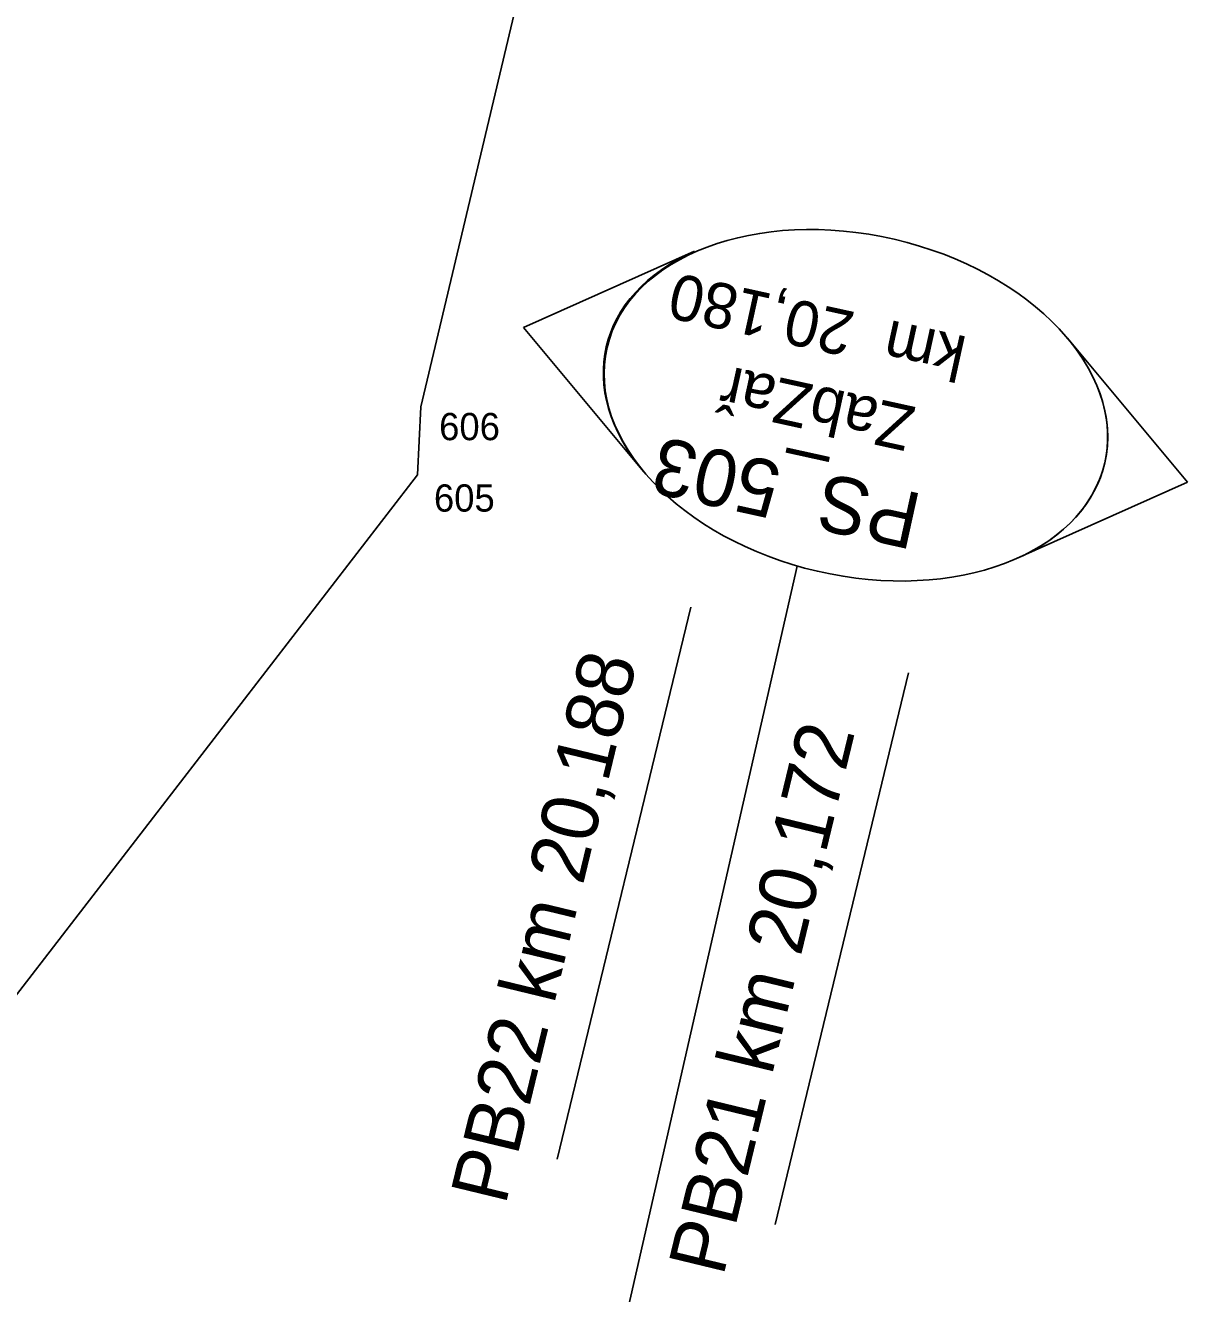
# Model space of a CAD drawing. Extents: x -748344 to -743169, y -1131966 to -1127091.
# Drawn here: x -747617.2 to -747566.1, y -1131689.4 to -1131633.6 of the extents above; entities that cross this region are included whole.
import ezdxf

# ---------------------------------------------------------------- set-up
doc = ezdxf.new("R2010")
doc.units = 0
for name, color, linetype in [('_Násyp', 7, 'Continuous'), ('_TRASA_vedení kabelu_CEZ', 7, 'Continuous'), ('bublina_fialová_čára_tenká', 7, 'Continuous'), ('bublina_růžová_230_čára_tučná', 7, 'Continuous'), ('křížky', 7, 'Continuous'), ('Nový stav', 7, 'Continuous'), ('Vrstva 60', 7, 'Continuous')]:
    doc.layers.add(name, color=color, linetype=linetype)

# ---------------------------------------------------------------- blocks, each defined once
blk = doc.blocks.new('POINT_DISPLAY')
blk.add_line((0, 0), (0, 0))

msp = doc.modelspace()

# ---------------------------------------------------------------- linework, layer by layer
at = {"layer": '_TRASA_vedení kabelu_CEZ'}
msp.add_lwpolyline([(-747606.661, -1131708.945), (-747603.525, -1131695.366), (-747628.041, -1131689.704), (-747599.968, -1131653.349), (-747599.823, -1131650.348), (-747590.152, -1131609.621), (-747577.851, -1131574.826), (-747576.114, -1131566.001), (-747573.02, -1131550.257), (-747574.144, -1131533.397), (-747574.335, -1131530.458), (-747575.576, -1131507.342), (-747576.376, -1131492.518), (-747578.396, -1131453.504)], dxfattribs=at)
at = {"layer": 'bublina_fialová_čára_tenká'}
msp.add_line((-747593.829, -1131703.744), (-747583.244, -1131657.359), dxfattribs=at)
at = {"layer": 'bublina_růžová_230_čára_tučná'}
for p, q in [((-747587.767, -1131643.498), (-747595.306, -1131646.86)), ((-747587.767, -1131643.498), (-747595.306, -1131646.86)), ((-747595.306, -1131646.86), (-747590.016, -1131653.196)), ((-747595.306, -1131646.86), (-747590.016, -1131653.196)), ((-747566.052, -1131653.671), (-747571.343, -1131647.335)), ((-747566.052, -1131653.671), (-747571.343, -1131647.335)), ((-747573.591, -1131657.033), (-747566.052, -1131653.671)), ((-747573.591, -1131657.033), (-747566.052, -1131653.671))]:
    msp.add_line(p, q, dxfattribs=at)
msp.add_ellipse((-747580.665, -1131650.283), major_axis=(-10.959, 2.541), ratio=0.666667, dxfattribs=at)
for centre, major_axis in [((-747580.694, -1131650.248), (-10.961, 2.541)), ((-747580.665, -1131650.283), (10.961, -2.541))]:
    msp.add_ellipse(centre, major_axis=major_axis, ratio=0.666473, start_param=5.557317, end_param=7.009053, dxfattribs=at)
at = {"layer": 'Nový stav'}
for p, q in [((-747593.819, -1131683.475), (-747587.939, -1131659.176)), ((-747584.225, -1131686.354), (-747578.345, -1131662.055))]:
    msp.add_line(p, q, dxfattribs=at)
at = {"layer": 'Vrstva 60'}
for p, q in [((-747599.823, -1131650.348), (-747599.823, -1131650.348)), ((-747599.968, -1131653.349), (-747599.968, -1131653.349))]:
    msp.add_line(p, q, dxfattribs=at)

# ---------------------------------------------------------------- block references
at = {"layer": 'křížky', "xscale": 10, "yscale": 10, "rotation": 61.14491455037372}
for p in [(-747599.823, -1131650.348), (-747599.968, -1131653.349)]:
    msp.add_blockref('POINT_DISPLAY', p, dxfattribs=at)

# ---------------------------------------------------------------- texts
at = {"layer": '_Násyp'}
for s, height, p in [('km  20,180', 2, (-747575.691, -1131647.284)), ('ZabZař', 2, (-747577.959, -1131650.378)), ('PS_503', 2.5, (-747577.658, -1131654.209))]:
    msp.add_text(s, height=height, rotation=167.6146, dxfattribs=at).set_placement(p)
at = {"layer": 'Nový stav'}
for s, rotation, p in [('PB22 km 20,188', 76.3964, (-747596.102, -1131685.539)), ('PB21 km 20,172', 76.395, (-747586.509, -1131688.672))]:
    msp.add_text(s, height=2.5, rotation=rotation, dxfattribs=at).set_placement(p)
at = {"layer": 'Vrstva 60'}
for s, p in [('606', (-747599.019, -1131651.82)), ('605', (-747599.248, -1131654.965))]:
    msp.add_text(s, height=1.2, dxfattribs=at).set_placement(p)

doc.saveas('drawing.dxf')
